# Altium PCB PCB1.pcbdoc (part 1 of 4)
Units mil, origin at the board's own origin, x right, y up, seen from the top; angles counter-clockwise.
Board outline 4701.34 x 4268.46 mil, 2 copper layers (Top Layer, Bottom Layer); 341 components, 58 nets, 1384 pads, 312 vias.
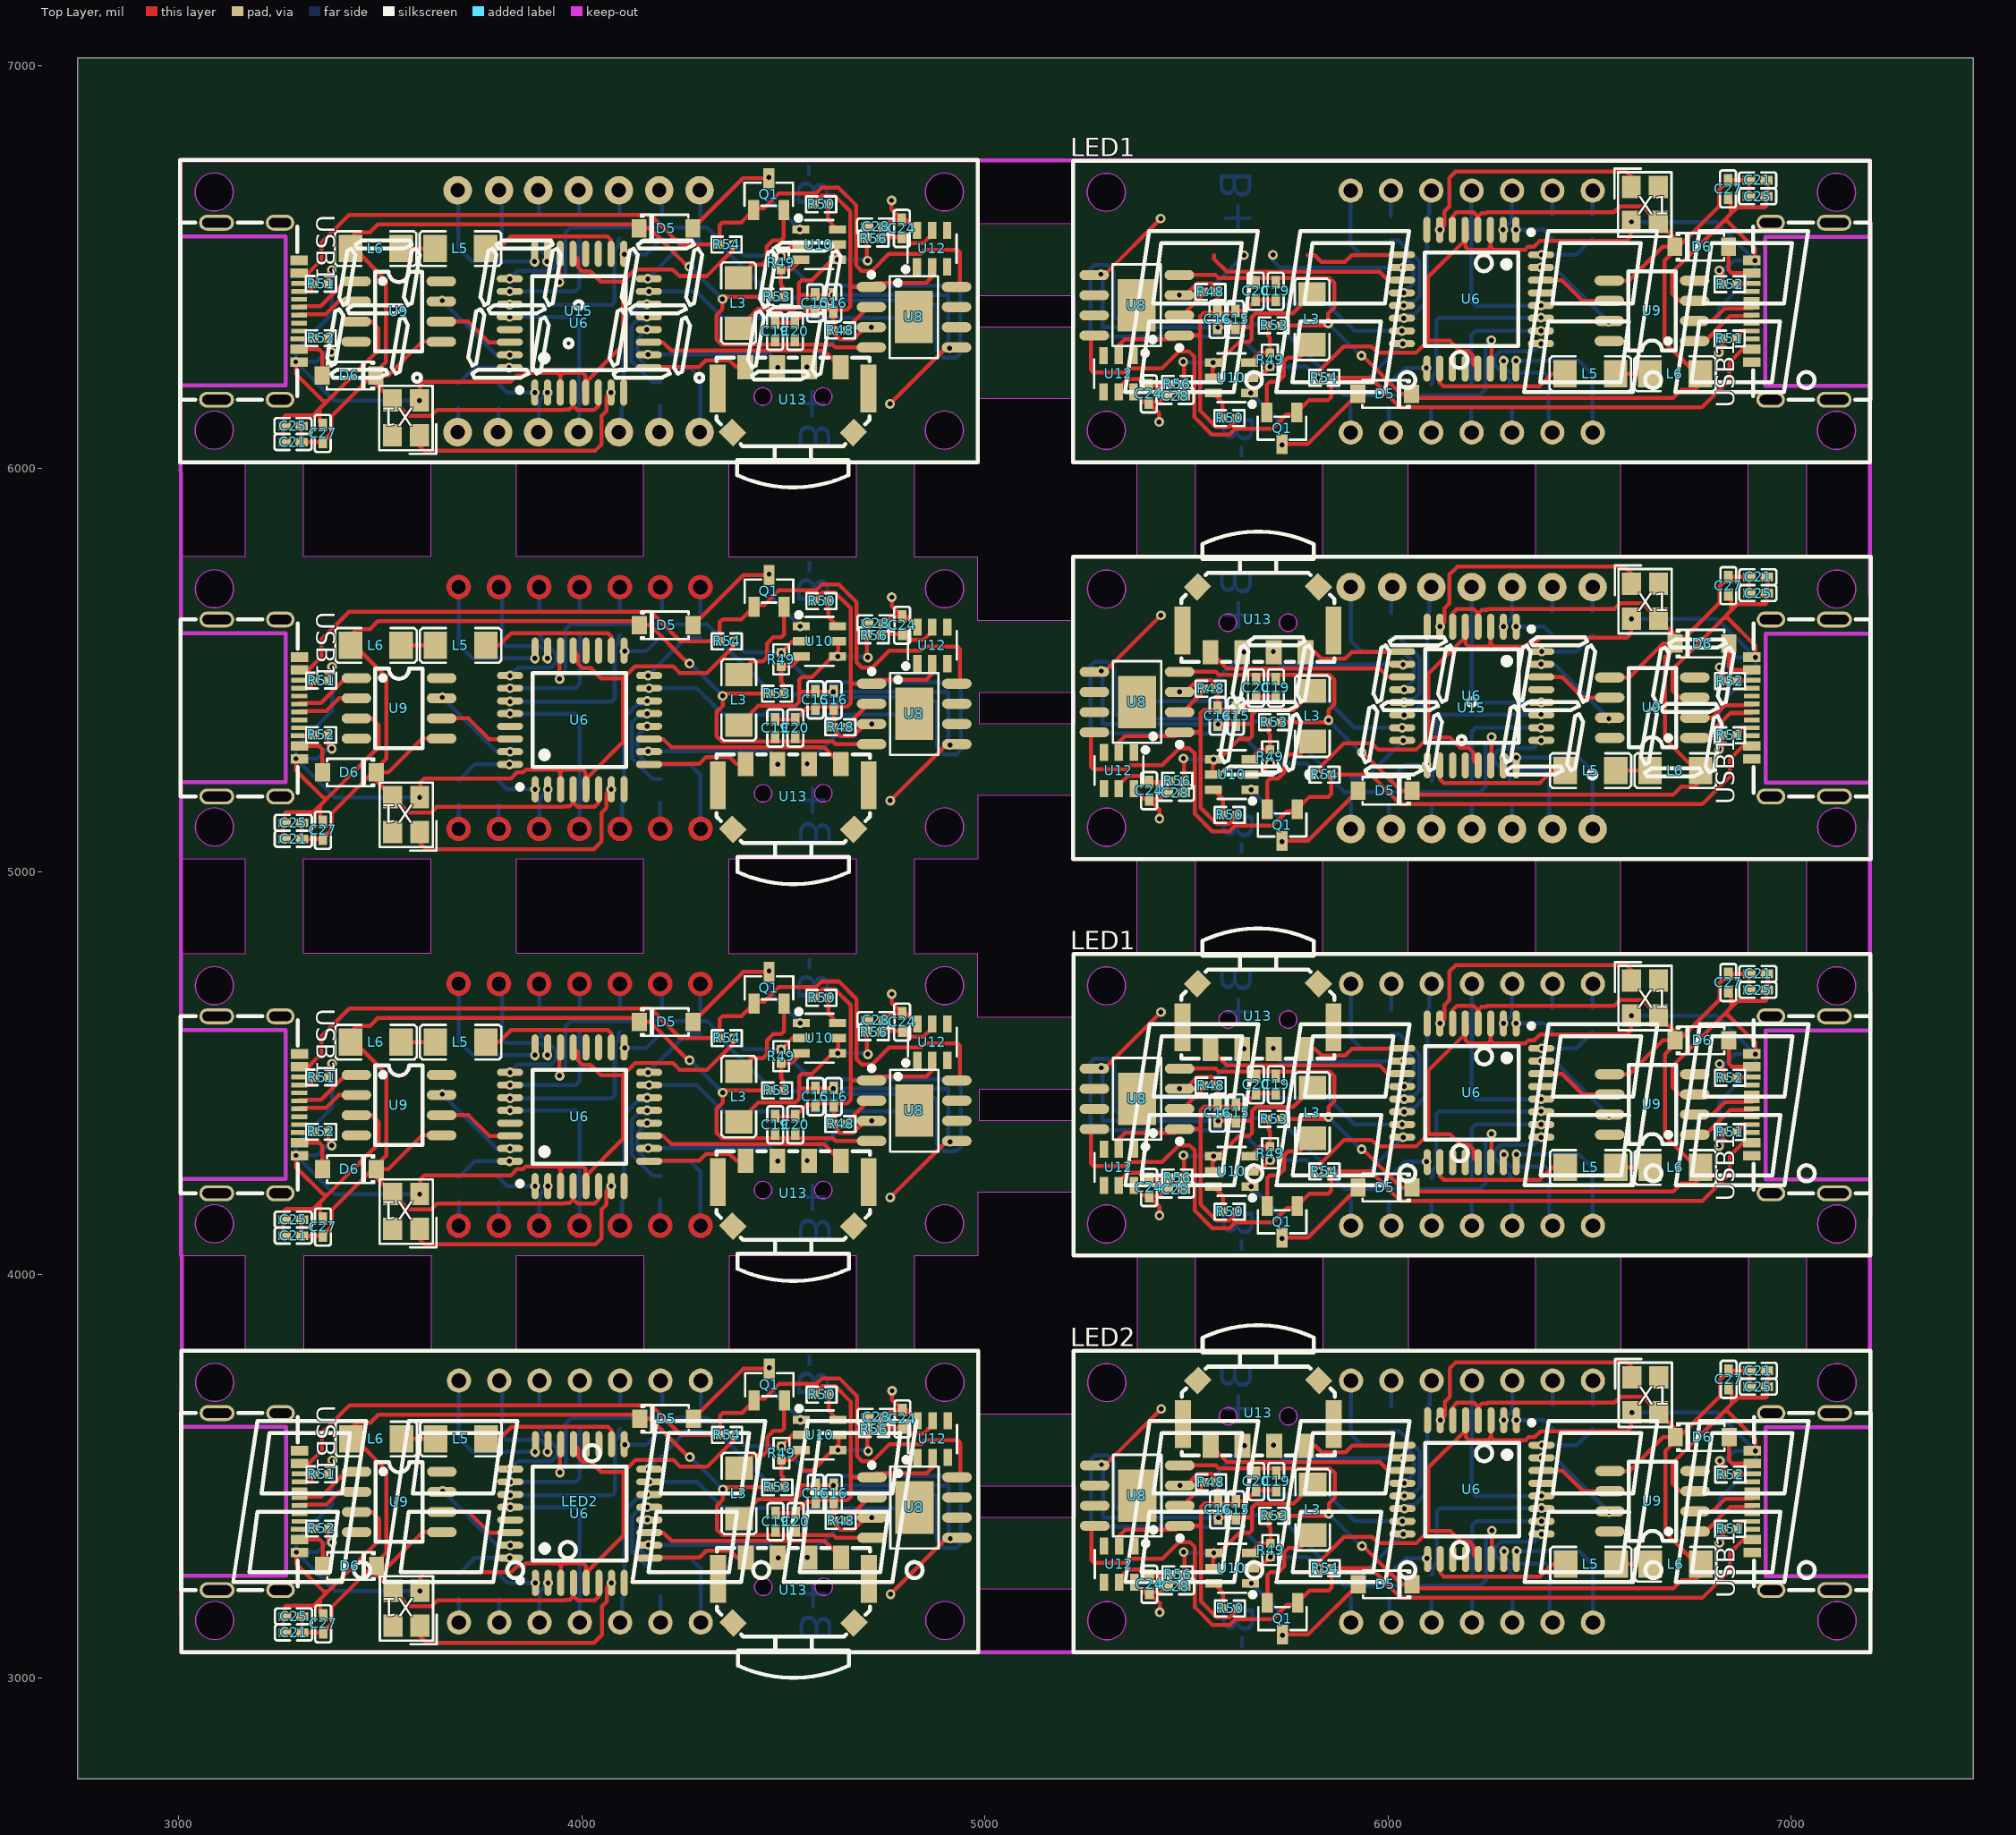
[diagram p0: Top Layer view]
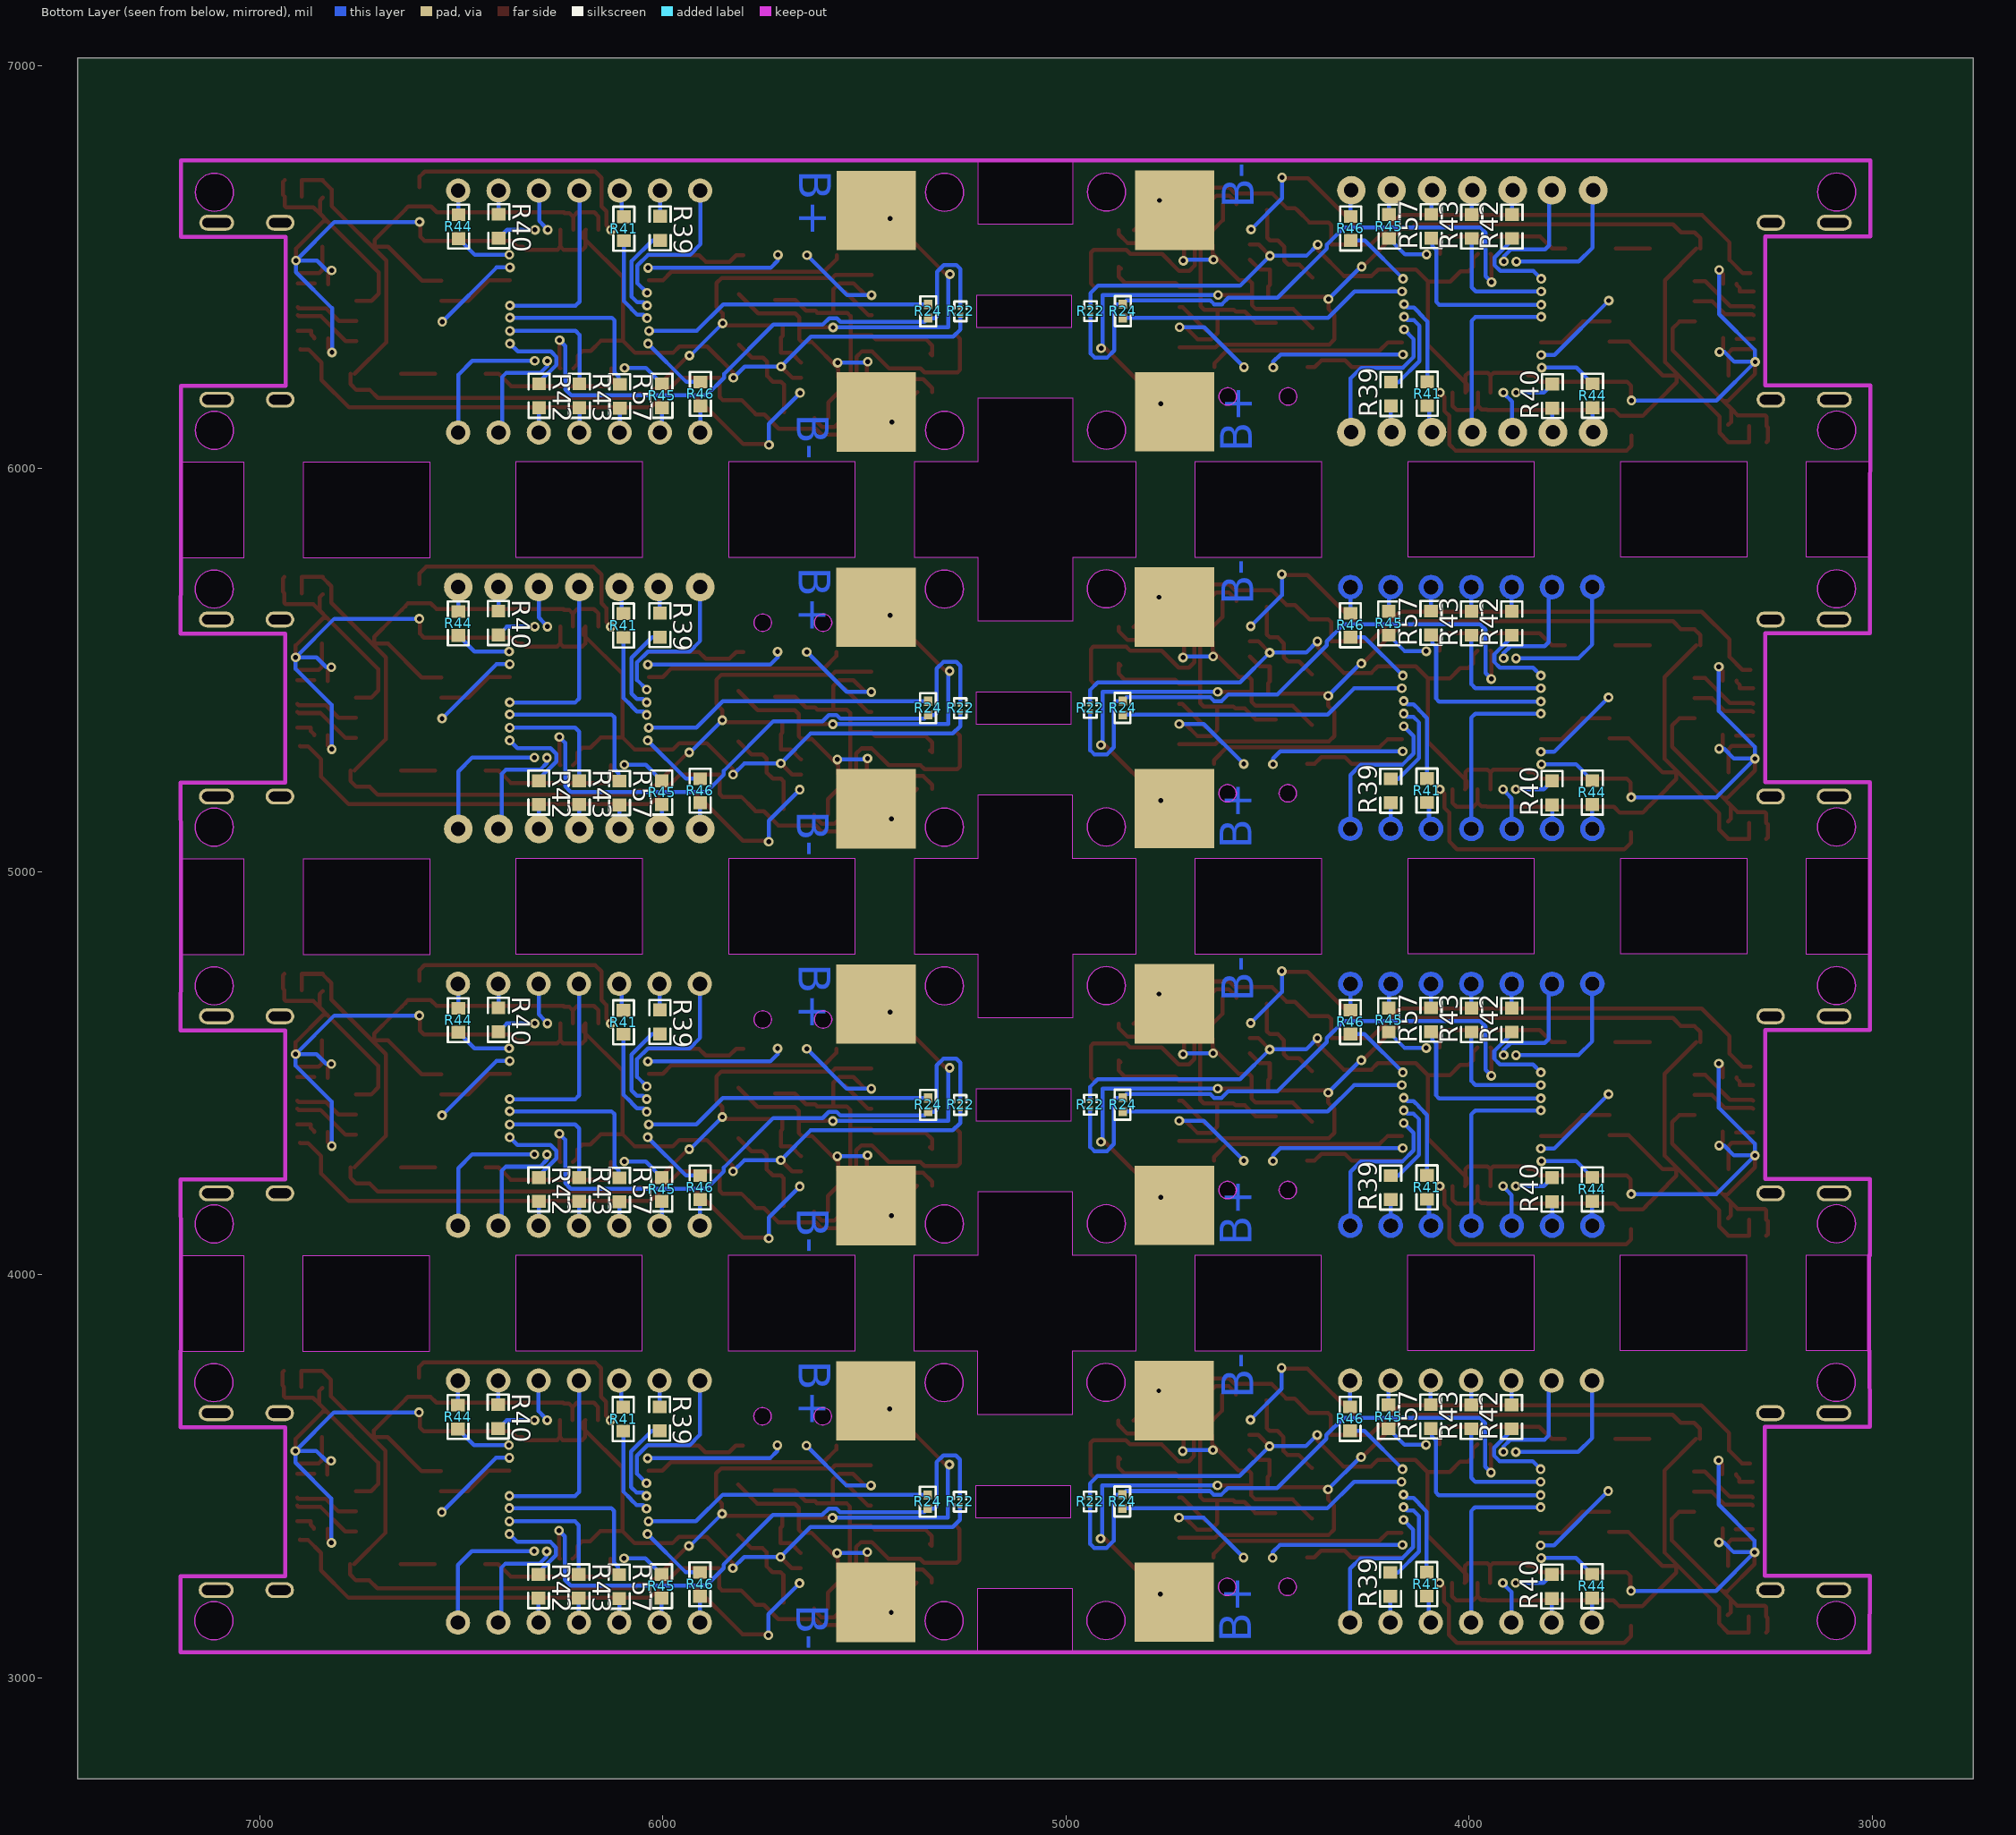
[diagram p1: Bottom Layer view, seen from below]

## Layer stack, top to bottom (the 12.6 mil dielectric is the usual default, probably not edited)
Top Layer: signal copper (thickness not stored)
Dielectric: dielectric 12.6, FR-4, Dk 4.8
Bottom Layer: signal copper (thickness not stored)

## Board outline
7451.34,2750 2750,2750 2750,7018.46 7451.34,7018.46
cut-out: 3136.51,5701.61 cw(c3089.27,5701.61) 3042.02,5701.61 cw(c3089.27,5701.61)
cut-out: 4947.53,5701.61 cw(c4900.29,5701.61) 4853.05,5701.61 cw(c4900.29,5701.61)
cut-out: 5349.12,5701.11 cw(c5301.87,5701.11) 5254.63,5701.11 cw(c5301.87,5701.11)
cut-out: 7160.14,5701.11 cw(c7112.9,5701.11) 7065.65,5701.11 cw(c7112.9,5701.11)
cut-out: 4987.01,5366.71 4987.01,5445.45 5223.23,5445.45 5223.23,5366.71
cut-out: 3136.51,4717.36 cw(c3089.27,4717.36) 3042.02,4717.36 cw(c3089.27,4717.36)
cut-out: 3448.26,5032.78 3625.43,5032.78 3625.43,4796.56 3310.47,4796.56 3310.47,5032.78
cut-out: 4522.97,5032.05 4680.45,5032.05 4680.45,4795.83 4365.49,4795.83 4365.49,5032.05
cut-out: 4947.53,4717.36 cw(c4900.29,4717.36) 4853.05,4717.36 cw(c4900.29,4717.36)
cut-out: 3971.89,5032.78 4152.99,5032.78 4152.99,4796.56 3838.03,4796.56 3838.03,5032.78
cut-out: 5349.12,4716.85 cw(c5301.87,4716.85) 5254.63,4716.85 cw(c5301.87,4716.85)
cut-out: 5679.92,5032.07 5837.4,5032.07 5837.4,4795.85 5522.44,4795.85 5522.44,5032.07
cut-out: 6207.48,5032.07 6364.96,5032.07 6364.96,4795.85 6050,4795.85 6050,5032.07
cut-out: 6734.94,5031.34 6892.42,5031.34 6892.42,4795.12 6577.46,4795.12 6577.46,5031.34
cut-out: 7160.14,4716.85 cw(c7112.9,4716.85) 7065.65,4716.85 cw(c7112.9,4716.85)
cut-out: 3136.51,5111.06 cw(c3089.27,5111.06) 3042.02,5111.06 cw(c3089.27,5111.06)
cut-out: 5376.77,4795.85 5219.29,4795.85 5219.29,4791.91 5219.19,4791.91 5219.19,4638.62 4982.97,4638.62 4982.97,4795.83 4826.12,4795.83 4825.59,4795.85 4825.59,5032.07 4983.07,5032.07 4983.07,5189.55 5219.29,5189.55 5219.29,5032.07 5376.77,5032.07
cut-out: 4947.53,5111.06 cw(c4900.29,5111.06) 4853.05,5111.06 cw(c4900.29,5111.06)
cut-out: 5349.12,5110.55 cw(c5301.87,5110.55) 5254.63,5110.55 cw(c5301.87,5110.55)
cut-out: 7160.14,5110.55 cw(c7112.9,5110.55) 7065.65,5110.55 cw(c7112.9,5110.55)
cut-out: 3136.51,4126.81 cw(c3089.27,4126.81) 3042.02,4126.81 cw(c3089.27,4126.81)
cut-out: 3539.48,3812.31 3311.14,3812.31 3311.14,4048.53 3626.1,4048.53 3626.1,3812.31
cut-out: 4523.64,4047.8 4681.12,4047.8 4681.12,3811.58 4366.16,3811.58 4366.16,4047.8
cut-out: 4947.53,4126.81 cw(c4900.29,4126.81) 4853.05,4126.81 cw(c4900.29,4126.81)
cut-out: 4063.11,3812.31 3838.7,3812.31 3838.7,4048.53 4153.66,4048.53 4153.66,3812.31
cut-out: 4987.01,4382.46 4987.01,4461.2 5223.23,4461.2 5223.23,4382.46
cut-out: 5349.12,4126.3 cw(c5301.87,4126.3) 5254.63,4126.3 cw(c5301.87,4126.3)
cut-out: 5653.03,4047.82 5838.07,4047.82 5838.07,3811.6 5523.11,3811.6 5523.11,4047.82
cut-out: 7160.14,4126.3 cw(c7112.9,4126.3) 7065.65,4126.3 cw(c7112.9,4126.3)
cut-out: 6208.15,4047.82 6365.63,4047.82 6365.63,3811.6 6050.67,3811.6 6050.67,4047.82
cut-out: 6735.61,4047.08 6893.09,4047.08 6893.09,3810.86 6578.13,3810.86 6578.13,4047.08
cut-out: 3137.18,3142.56 cw(c3089.94,3142.56) 3042.69,3142.56 cw(c3089.94,3142.56)
cut-out: 4948.2,3142.56 cw(c4900.96,3142.56) 4853.71,3142.56 cw(c4900.96,3142.56)
cut-out: 4987.68,3398.21 4987.68,3476.95 5223.9,3476.95 5223.9,3398.21
cut-out: 5349.78,3142.05 cw(c5302.54,3142.05) 5255.3,3142.05 cw(c5302.54,3142.05)
cut-out: 7160.81,3142.05 cw(c7113.56,3142.05) 7066.32,3142.05 cw(c7113.56,3142.05)
cut-out: 3137.18,3733.11 cw(c3089.94,3733.11) 3042.69,3733.11 cw(c3089.94,3733.11)
cut-out: 5219.29,4205.3 5219.29,4047.82 5377.44,4047.82 5377.44,3811.6 5219.96,3811.6 5219.96,3807.66 5219.86,3807.66 5219.86,3654.37 4983.64,3654.37 4983.64,3811.58 4826.79,3811.58 4826.26,3811.6 4826.26,4047.82 4983.07,4047.82 4983.07,4205.3
cut-out: 4948.2,3733.11 cw(c4900.96,3733.11) 4853.71,3733.11 cw(c4900.96,3733.11)
cut-out: 5349.78,3732.6 cw(c5302.54,3732.6) 5255.3,3732.6 cw(c5302.54,3732.6)
cut-out: 7160.81,3732.6 cw(c7113.56,3732.6) 7066.32,3732.6 cw(c7113.56,3732.6)
cut-out: 3135.84,6095.32 cw(c3088.6,6095.32) 3041.35,6095.32 cw(c3088.6,6095.32)
cut-out: 3135.84,6685.87 cw(c3088.6,6685.87) 3041.35,6685.87 cw(c3088.6,6685.87)
cut-out: 3538.82,5780.82 3310.47,5780.82 3310.47,6017.04 3625.43,6017.04 3625.43,5780.82
cut-out: 4062.44,5780.82 3838.03,5780.82 3838.03,6017.04 4152.99,6017.04 4152.99,5780.82
cut-out: 4946.87,6095.32 cw(c4899.62,6095.32) 4852.38,6095.32 cw(c4899.62,6095.32)
cut-out: 4946.87,6685.87 cw(c4899.62,6685.87) 4852.38,6685.87 cw(c4899.62,6685.87)
cut-out: 4986.34,6350.97 4986.34,6429.71 5222.56,6429.71 5222.56,6350.97
cut-out: 5348.45,6685.36 cw(c5301.2,6685.36) 5253.96,6685.36 cw(c5301.2,6685.36)
cut-out: 5348.45,6094.81 cw(c5301.2,6094.81) 5253.96,6094.81 cw(c5301.2,6094.81)
cut-out: 5652.36,6016.32 5837.4,6016.32 5837.4,5780.1 5522.44,5780.1 5522.44,6016.32
cut-out: 6207.48,6016.32 6364.96,6016.32 6364.96,5780.1 6050,5780.1 6050,6016.32
cut-out: 6734.94,6015.59 6892.42,6015.59 6892.42,5779.37 6577.46,5779.37 6577.46,6015.59
cut-out: 7159.47,6685.36 cw(c7112.23,6685.36) 7064.98,6685.36 cw(c7112.23,6685.36)
cut-out: 7159.47,6094.81 cw(c7112.23,6094.81) 7064.98,6094.81 cw(c7112.23,6094.81)
cut-out: 5218.52,6760.42 5218.52,6607.13 4982.3,6607.13 4982.3,6764.34 4983.33,6764.35 5218.62,6764.35 5218.62,6760.42
cut-out: 7195.57,6015.59 7195.57,5779.37 7038.09,5779.37 7038.09,6015.59
cut-out: 4680.45,6016.3 4680.45,5780.08 4365.49,5780.08 4365.49,6016.3
cut-out: 5219.19,5776.16 5219.19,5622.87 4982.97,5622.87 4982.97,5780.08 4826.12,5780.08 4825.59,5780.1 4825.59,6016.32 4982.4,6016.32 4982.4,6173.8 5218.62,6173.8 5218.62,6016.32 5376.77,6016.32 5376.77,5780.1 5219.29,5780.1 5219.29,5776.16
cut-out: 3165.47,4048.53 3165.47,3812.31 3007.99,3812.31 3007.99,4048.53
cut-out: 5219.96,3221.04 5219.96,3063.56 4983.74,3063.56 4983.74,3221.04
cut-out: 7038.76,3810.86 7038.76,4047.08 7196.24,4047.08 7196.24,3810.86
cut-out: 3006.59,4796.1 3006.59,5032.32 3164.8,5032.78 3164.8,4795.89 3164.59,4796.1
cut-out: 7195.57,5031.34 7195.57,4795.12 7038.09,4795.12 7038.09,5031.34
cut-out: 3003.38,5780.82 3003.38,6017.04 3164.8,6017.04 3164.8,5780.82

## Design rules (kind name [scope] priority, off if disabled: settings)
BoardOutlineClearance copperThickness1oz [All] p0: genericclearance=10 ignorepadtopadclearanceinfootprint=FALSE except(0: Arc-SplitContinuation Track-SplitContinuation SMDPad-SplitContinuation THPad-SplitContinuation Via-SplitContinuation Fill-SplitContinuation Poly-SplitContinuation Region-SplitContinuation Text-SplitContinuation; 6: Track-CutoutEdge SMDPad-CutoutEdge THPad-CutoutEdge Via-CutoutEdge Region-CutoutEdge; 11.8: Track-OutlineEdge SMDPad-OutlineEdge THPad-OutlineEdge Via-OutlineEdge Fill-OutlineEdge Region-OutlineEdge Poly-OutlineEdge Text-OutlineEdge Fill-CutoutEdge)
BoardOutlineClearance copperThickness2oz [All] p0: genericclearance=10 ignorepadtopadclearanceinfootprint=FALSE except(0: Arc-SplitContinuation Track-SplitContinuation SMDPad-SplitContinuation THPad-SplitContinuation Via-SplitContinuation Fill-SplitContinuation Poly-SplitContinuation Region-SplitContinuation Text-SplitContinuation; 6: Track-CutoutEdge SMDPad-CutoutEdge THPad-CutoutEdge Via-CutoutEdge Region-CutoutEdge; 11.8: Track-OutlineEdge SMDPad-OutlineEdge THPad-OutlineEdge Via-OutlineEdge Fill-OutlineEdge Region-OutlineEdge Poly-OutlineEdge Text-OutlineEdge Fill-CutoutEdge)
Clearance copperThickness1oz [(InNet('POWER_VBUS') OR InNet('BATT') OR InNet('$1N14246') OR InNet('POWER_GND') OR InNet('$1N14266') OR InNet('$1N10863') OR InNet('+5V') OR InNet('D7') OR InNet('$1N7885') OR InNet('$1N11526') OR InNet('$1N13433') OR InNet('$1N13465') OR InNet('D5') OR InNet('$1N11705') OR InNet('XTAL1') OR InNet('A7') OR InNet('RX') OR InNet('$1N13291') OR InNet('D+') OR InNet('D-') OR InNet('$1N3744') OR InNet('D6') OR InNet('$1N25016') OR InNet('D8') OR InNet('D12') OR InNet('$1N25014') OR InNet('$1N25004') OR InNet('D9') OR InNet('D13') OR InNet('D11') OR InNet('D10') OR InNet('$1N25012') OR InNet('$1N26871') OR InNet('A4') OR InNet('$1N25022') OR InNet('A3') OR InNet('A2') OR InNet('A0') OR InNet('D4') OR InNet('$1N25024') OR InNet('D3') OR InNet('A1') OR InNet('$1N25008') OR InNet('D2') OR InNet('TX') OR InNet('$1N25046') OR InNet('A5') OR InNet('A6') OR InNet('$1N29845') OR InNet('$1N31836') OR InNet('$1N31834') OR InNet('$1N31838') OR InNet('$1N31830') OR InNet('$1N31828') OR InNet('$1N31832') OR InNet('$1N31824') OR InNet('$1N31826') OR InNet('$1N31822'))] p1: gap=7 ignorepadtopadclearanceinfootprint=FALSE except(4: Track-Track; 6: Track-SMDPad SMDPad-SMDPad Track-THPad SMDPad-THPad THPad-THPad Track-Via SMDPad-Via THPad-Via Via-Via SMDPad-Fill THPad-Fill Via-Fill Fill-Fill Track-Region SMDPad-Region THPad-Region Via-Region Region-Region Track-Poly SMDPad-Poly THPad-Poly Via-Poly Fill-Poly Region-Poly Poly-Poly Track-Text SMDPad-Text THPad-Text Via-Text Fill-Text Region-Text Poly-Text Text-Text; 6.9: Track-Hole SMDPad-Hole THPad-Hole Via-Hole Fill-Hole Region-Hole Poly-Hole Text-Hole Sheet-Hole; 11.8: Track-Fill Fill-Region Track-Sheet SMDPad-Sheet THPad-Sheet Via-Sheet Fill-Sheet Region-Sheet Poly-Sheet Text-Sheet)
Clearance copperThickness2oz [All] p1: gap=7 ignorepadtopadclearanceinfootprint=FALSE except(6: Track-SMDPad SMDPad-SMDPad Track-THPad SMDPad-THPad THPad-THPad Track-Via SMDPad-Via THPad-Via Via-Via SMDPad-Fill THPad-Fill Via-Fill Fill-Fill Track-Region SMDPad-Region THPad-Region Via-Region Region-Region Track-Poly SMDPad-Poly THPad-Poly Via-Poly Fill-Poly Region-Poly Poly-Poly Track-Text SMDPad-Text THPad-Text Via-Text Fill-Text Region-Text Poly-Text Text-Text; 6.9: Track-Hole SMDPad-Hole THPad-Hole Via-Hole Fill-Hole Region-Hole Poly-Hole Text-Hole Sheet-Hole; 8: Track-Track; 11.8: Track-Fill Fill-Region Track-Sheet SMDPad-Sheet THPad-Sheet Via-Sheet Fill-Sheet Region-Sheet Poly-Sheet Text-Sheet)
DiffPairsRouting differentialPair [All] p1: maxuncoupledlength=10 minlimit=6 maxlimit=6 mostfreqgap=6 toplayer_minwidth=5 toplayer_prefwidth=10 toplayer_maxwidth=100 bottomlayer_minwidth=5 bottomlayer_prefwidth=10 bottomlayer_maxwidth=100
PasteMaskExpansion pasteMaskExpansion [All] p1: expansion=0
PlaneConnect innerPlane [All] p1: planeconnectstyle=Relief reliefexpansion=20 reliefentries=4 reliefconductorwidth=10 reliefairgap=10
PolygonConnect copperRegion [All] p1: connectstyle=Relief reliefentries=4 reliefconductorwidth=10 polygonreliefangle="90 Angle" airgapwidth=10
RoutingVias viaSize [All] p1: viastyle="Through Hole" holewidth=12.0078 minholewidth=11.811 maxholewidth=248.0314 width=24.0158 minwidth=19.685 maxwidth=393.7008
SolderMaskExpansion solderMaskExpansion [All] p1: useseparateexpansions=TRUE expansion=2 expansionbottom=2
Width copperThickness1oz [All] p1: maxlimit=100 minlimit=5 preferedwidth=10
Width copperThickness2oz [All] p1: maxlimit=100 minlimit=8 preferedwidth=10

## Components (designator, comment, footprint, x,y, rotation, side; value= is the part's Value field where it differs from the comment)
C15 "CL05A475MQ5NRNC_C307423" C0402 5623.05,3417.33 r90 top
C15 "CL05A475MQ5NRNC_C307423" C0402 4580.45,3457.83 r270 top
C15 "CL05A475MQ5NRNC_C307423" C0402 4579.78,4442.09 r270 top
C15 "CL05A475MQ5NRNC_C307423" C0402 5622.38,4401.58 r90 top
C15 "CL05A475MQ5NRNC_C307423" C0402 4579.78,5426.34 r270 top
C15 "CL05A475MQ5NRNC_C307423" C0402 5622.38,5385.83 r90 top
C15 "CL05A475MQ5NRNC_C307423" C0402 4579.11,6410.59 r270 top
C15 "CL05A475MQ5NRNC_C307423" C0402 5621.72,6370.08 r90 top
C16 "CL05A475MQ5NRNC_C307423" C0402 5578.05,3417.33 r90 top
C16 "CL05A475MQ5NRNC_C307423" C0402 4625.45,3457.83 r270 top
C16 "CL05A475MQ5NRNC_C307423" C0402 4624.78,4442.09 r270 top
C16 "CL05A475MQ5NRNC_C307423" C0402 5577.38,4401.58 r90 top
C16 "CL05A475MQ5NRNC_C307423" C0402 4624.78,5426.34 r270 top
C16 "CL05A475MQ5NRNC_C307423" C0402 5577.38,5385.83 r90 top
C16 "CL05A475MQ5NRNC_C307423" C0402 4624.11,6410.59 r270 top
C16 "CL05A475MQ5NRNC_C307423" C0402 5576.72,6370.08 r90 top
C19 "CL05A475MQ5NRNC_C307423" C0402 5722.59,3487.33 r90 top
C19 "CL05A475MQ5NRNC_C307423" C0402 4480.91,3387.83 r270 top
C19 "CL05A475MQ5NRNC_C307423" C0402 4480.24,4372.09 r270 top
C19 "CL05A475MQ5NRNC_C307423" C0402 5721.92,4471.58 r90 top
C19 "CL05A475MQ5NRNC_C307423" C0402 4480.24,5356.34 r270 top
C19 "CL05A475MQ5NRNC_C307423" C0402 5721.92,5455.83 r90 top
C19 "CL05A475MQ5NRNC_C307423" C0402 4479.57,6340.59 r270 top
C19 "CL05A475MQ5NRNC_C307423" C0402 5721.26,6440.08 r90 top
C20 "CL05A475MQ5NRNC_C307423" C0402 5673.05,3487.33 r90 top
C20 "CL05A475MQ5NRNC_C307423" C0402 4530.45,3387.83 r270 top
C20 "CL05A475MQ5NRNC_C307423" C0402 4529.78,4372.09 r270 top
C20 "CL05A475MQ5NRNC_C307423" C0402 5672.38,4471.58 r90 top
C20 "CL05A475MQ5NRNC_C307423" C0402 4529.78,5356.34 r270 top
C20 "CL05A475MQ5NRNC_C307423" C0402 5672.38,5455.83 r90 top
C20 "CL05A475MQ5NRNC_C307423" C0402 4529.11,6340.59 r270 top
C20 "CL05A475MQ5NRNC_C307423" C0402 5671.72,6440.08 r90 top
C21 "CL05A475MQ5NRNC_C307423" C0402 6918.05,3762.33 r0 top
C21 "CL05A475MQ5NRNC_C307423" C0402 3285.45,3112.83 r180 top
C21 "CL05A475MQ5NRNC_C307423" C0402 3284.78,4097.09 r180 top
C21 "CL05A475MQ5NRNC_C307423" C0402 6917.38,4746.58 r0 top
C21 "CL05A475MQ5NRNC_C307423" C0402 3284.78,5081.34 r180 top
C21 "CL05A475MQ5NRNC_C307423" C0402 6917.38,5730.83 r0 top
C21 "CL05A475MQ5NRNC_C307423" C0402 3284.11,6065.59 r180 top
C21 "CL05A475MQ5NRNC_C307423" C0402 6916.72,6715.08 r0 top
C24 "FCC0402B104K160AT" C0402 5408.05,3232.33 r270 top
C24 "FCC0402B104K160AT" C0402 4795.45,3642.83 r90 top
C24 "FCC0402B104K160AT" C0402 4794.78,4627.09 r90 top
C24 "FCC0402B104K160AT" C0402 5407.38,4216.58 r270 top
C24 "FCC0402B104K160AT" C0402 4794.78,5611.34 r90 top
C24 "FCC0402B104K160AT" C0402 5407.38,5200.83 r270 top
C24 "FCC0402B104K160AT" C0402 4794.11,6595.59 r90 top
C24 "FCC0402B104K160AT" C0402 5406.72,6185.08 r270 top
C25 "CL05A475MQ5NRNC_C307423" C0402 6918.05,3722.33 r180 top
C25 "CL05A475MQ5NRNC_C307423" C0402 3285.45,3152.83 r0 top
C25 "CL05A475MQ5NRNC_C307423" C0402 3284.78,4137.09 r0 top
C25 "CL05A475MQ5NRNC_C307423" C0402 6917.38,4706.58 r180 top
C25 "CL05A475MQ5NRNC_C307423" C0402 3284.78,5121.34 r0 top
C25 "CL05A475MQ5NRNC_C307423" C0402 6917.38,5690.83 r180 top
C25 "CL05A475MQ5NRNC_C307423" C0402 3284.11,6105.59 r0 top
C25 "CL05A475MQ5NRNC_C307423" C0402 6916.72,6675.08 r180 top
C27 "CL05A475MQ5NRNC_C307423" C0402 6844.51,3740.87 r90 top
C27 "CL05A475MQ5NRNC_C307423" C0402 3358.99,3134.29 r270 top
C27 "CL05A475MQ5NRNC_C307423" C0402 3358.32,4118.55 r270 top
C27 "CL05A475MQ5NRNC_C307423" C0402 6843.84,4725.12 r90 top
C27 "CL05A475MQ5NRNC_C307423" C0402 3358.32,5102.8 r270 top
C27 "CL05A475MQ5NRNC_C307423" C0402 6843.84,5709.37 r90 top
C27 "CL05A475MQ5NRNC_C307423" C0402 3357.65,6087.05 r270 top
C27 "CL05A475MQ5NRNC_C307423" C0402 6843.18,6693.62 r90 top
C28 "CL05A475MQ5NRNC_C307423" C0402 5473.05,3227.33 r0 top
C28 "CL05A475MQ5NRNC_C307423" C0402 4730.45,3647.83 r180 top
C28 "CL05A475MQ5NRNC_C307423" C0402 4729.78,4632.09 r180 top
C28 "CL05A475MQ5NRNC_C307423" C0402 5472.38,4211.58 r0 top
C28 "CL05A475MQ5NRNC_C307423" C0402 4729.78,5616.34 r180 top
C28 "CL05A475MQ5NRNC_C307423" C0402 5472.38,5195.83 r0 top
C28 "CL05A475MQ5NRNC_C307423" C0402 4729.11,6600.59 r180 top
C28 "CL05A475MQ5NRNC_C307423" C0402 5471.72,6180.08 r0 top
D5 "DSK34_C41029" SOD-123_L2.8-W1.8-LS3.7-RD 5993.05,3232.33 r180 top
D5 "DSK34_C41029" SOD-123_L2.8-W1.8-LS3.7-RD 4210.45,3642.83 r0 top
D5 "DSK34_C41029" SOD-123_L2.8-W1.8-LS3.7-RD 4209.78,4627.09 r0 top
D5 "DSK34_C41029" SOD-123_L2.8-W1.8-LS3.7-RD 5992.38,4216.58 r180 top
D5 "DSK34_C41029" SOD-123_L2.8-W1.8-LS3.7-RD 4209.78,5611.34 r0 top
D5 "DSK34_C41029" SOD-123_L2.8-W1.8-LS3.7-RD 5992.38,5200.83 r180 top
D5 "DSK34_C41029" SOD-123_L2.8-W1.8-LS3.7-RD 4209.11,6595.59 r0 top
D5 "DSK34_C41029" SOD-123_L2.8-W1.8-LS3.7-RD 5991.72,6185.08 r180 top
D6 "DSK34_C41029" SOD-123_L2.8-W1.8-LS3.7-RD 6779.12,3597.33 r0 top
D6 "DSK34_C41029" SOD-123_L2.8-W1.8-LS3.7-RD 3424.38,3277.83 r180 top
D6 "DSK34_C41029" SOD-123_L2.8-W1.8-LS3.7-RD 3423.72,4262.09 r180 top
D6 "DSK34_C41029" SOD-123_L2.8-W1.8-LS3.7-RD 6778.45,4581.58 r0 top
D6 "DSK34_C41029" SOD-123_L2.8-W1.8-LS3.7-RD 3423.72,5246.34 r180 top
D6 "DSK34_C41029" SOD-123_L2.8-W1.8-LS3.7-RD 6778.45,5565.83 r0 top
D6 "DSK34_C41029" SOD-123_L2.8-W1.8-LS3.7-RD 3423.05,6230.59 r180 top
D6 "DSK34_C41029" SOD-123_L2.8-W1.8-LS3.7-RD 6777.78,6550.08 r0 top
L3 "CMI321609U4R7KT" L1206 5813.05,3417.33 r270 top
L3 "CMI321609U4R7KT" L1206 4390.45,3457.83 r90 top
L3 "CMI321609U4R7KT" L1206 4389.78,4442.09 r90 top
L3 "CMI321609U4R7KT" L1206 5812.38,4401.58 r270 top
L3 "CMI321609U4R7KT" L1206 4389.78,5426.34 r90 top
L3 "CMI321609U4R7KT" L1206 5812.38,5385.83 r270 top
L3 "CMI321609U4R7KT" L1206 4389.11,6410.59 r90 top
L3 "CMI321609U4R7KT" L1206 5811.72,6370.08 r270 top
L5 "CMI321609U4R7KT" L1206 6503.05,3282.33 r180 top
L5 "CMI321609U4R7KT" L1206 3700.45,3592.83 r0 top
L5 "CMI321609U4R7KT" L1206 3699.78,4577.09 r0 top
L5 "CMI321609U4R7KT" L1206 6502.38,4266.58 r180 top
L5 "CMI321609U4R7KT" L1206 3699.78,5561.34 r0 top
L5 "CMI321609U4R7KT" L1206 6502.38,5250.83 r180 top
L5 "CMI321609U4R7KT" L1206 3699.11,6545.59 r0 top
L5 "CMI321609U4R7KT" L1206 6501.72,6235.08 r180 top
L6 "CMI321609U4R7KT" L1206 6713.05,3282.33 r180 top
L6 "CMI321609U4R7KT" L1206 3490.45,3592.83 r0 top
L6 "CMI321609U4R7KT" L1206 3489.78,4577.09 r0 top
L6 "CMI321609U4R7KT" L1206 6712.38,4266.58 r180 top
L6 "CMI321609U4R7KT" L1206 3489.78,5561.34 r0 top
L6 "CMI321609U4R7KT" L1206 6712.38,5250.83 r180 top
L6 "CMI321609U4R7KT" L1206 3489.11,6545.59 r0 top
L6 "CMI321609U4R7KT" L1206 6711.72,6235.08 r180 top
LED1 "SLR0564DBA4BD" LED-SEG-TH_SLR0564DBA4BD 6208.15,4421.83 r0 top
LED1 "SLR0564DBA4BD" LED-SEG-TH_SLR0564DBA4BD 6207.45,6389.45 r0 top
LED2 "SLRR0564DY2C4BD-6.3" LED-SEG-TH_SLRR0564DY2C4BD-6.3 6208.15,3437.58 r0 top
LED2 "SLRR0564DY2C4BD-6.3" LED-SEG-TH_SLRR0564DY2C4BD-6.3 3995.55,3437.58 r0 top
Q1 "IRLML6401_C5190144" SOT-23-3_L2.9-W1.3-P1.90-LS2.4-BR 5738.05,3147.33 r90 top
Q1 "IRLML6401_C5190144" SOT-23-3_L2.9-W1.3-P1.90-LS2.4-BR 4465.45,3727.83 r270 top
Q1 "IRLML6401_C5190144" SOT-23-3_L2.9-W1.3-P1.90-LS2.4-BR 4464.78,4712.09 r270 top
Q1 "IRLML6401_C5190144" SOT-23-3_L2.9-W1.3-P1.90-LS2.4-BR 5737.38,4131.58 r90 top
Q1 "IRLML6401_C5190144" SOT-23-3_L2.9-W1.3-P1.90-LS2.4-BR 4464.78,5696.34 r270 top
Q1 "IRLML6401_C5190144" SOT-23-3_L2.9-W1.3-P1.90-LS2.4-BR 5737.38,5115.83 r90 top
Q1 "IRLML6401_C5190144" SOT-23-3_L2.9-W1.3-P1.90-LS2.4-BR 4464.11,6680.59 r270 top
Q1 "IRLML6401_C5190144" SOT-23-3_L2.9-W1.3-P1.90-LS2.4-BR 5736.72,6100.08 r90 top
R22 "100k" R0201 5263.05,3437.33 r270 bottom
R22 "100k" R0201 4940.45,3437.83 r90 bottom
R22 "100k" R0201 4939.78,4422.09 r90 bottom
R22 "100k" R0201 5262.38,4421.58 r270 bottom
R22 "100k" R0201 4939.78,5406.34 r90 bottom
R22 "100k" R0201 5262.38,5405.83 r270 bottom
R22 "100k" R0201 4939.11,6390.59 r90 bottom
R22 "100k" R0201 5261.72,6390.08 r270 bottom
R24 "0402WGF1003TCE" R0402 5343.05,3437.33 r270 bottom
R24 "0402WGF1003TCE" R0402 4860.45,3437.83 r90 bottom
R24 "0402WGF1003TCE" R0402 4859.78,4422.09 r90 bottom
R24 "0402WGF1003TCE" R0402 5342.38,4421.58 r270 bottom
R24 "0402WGF1003TCE" R0402 4859.78,5406.34 r90 bottom
R24 "0402WGF1003TCE" R0402 5342.38,5405.83 r270 bottom
R24 "0402WGF1003TCE" R0402 4859.11,6390.59 r90 bottom
R24 "0402WGF1003TCE" R0402 5341.72,6390.08 r270 bottom
R39 "FRC0603F1001TS" R0603 6008.05,3643.01 r270 bottom
R39 "FRC0603F1001TS" R0603 4195.45,3232.15 r90 bottom
R39 "FRC0603F1001TS" R0603 4194.78,4216.41 r90 bottom
R39 "FRC0603F1001TS" R0603 6007.38,4627.26 r270 bottom
R39 "FRC0603F1001TS" R0603 4194.78,5200.66 r90 bottom
R39 "FRC0603F1001TS" R0603 6007.38,5611.51 r270 bottom
R39 "FRC0603F1001TS" R0603 4194.11,6184.91 r90 bottom
R39 "FRC0603F1001TS" R0603 6006.72,6595.76 r270 bottom
R40 "FRC0603F1001TS" R0603 6408.29,3648.23 r270 bottom
R40 "FRC0603F1001TS" R0603 3795.21,3226.93 r90 bottom
R40 "FRC0603F1001TS" R0603 3794.54,4211.18 r90 bottom
R40 "FRC0603F1001TS" R0603 6407.63,4632.48 r270 bottom
R40 "FRC0603F1001TS" R0603 3794.54,5195.43 r90 bottom
R40 "FRC0603F1001TS" R0603 6407.63,5616.74 r270 bottom
R40 "FRC0603F1001TS" R0603 3793.87,6179.68 r90 bottom
R40 "FRC0603F1001TS" R0603 6406.96,6600.99 r270 bottom
R41 "FRC0603F1001TS" R0603 6098.05,3642.33 r270 bottom
R41 "FRC0603F1001TS" R0603 4105.45,3232.83 r90 bottom
R41 "FRC0603F1001TS" R0603 4104.78,4217.09 r90 bottom
R41 "FRC0603F1001TS" R0603 6097.38,4626.58 r270 bottom
R41 "FRC0603F1001TS" R0603 4104.78,5201.34 r90 bottom
R41 "FRC0603F1001TS" R0603 6097.38,5610.83 r270 bottom
R41 "FRC0603F1001TS" R0603 4104.11,6185.59 r90 bottom
R41 "FRC0603F1001TS" R0603 6096.72,6595.08 r270 bottom
R42 "FRC0603F1001TS" R0603 6308.29,3227.55 r270 bottom
R42 "FRC0603F1001TS" R0603 3895.21,3647.61 r90 bottom
R42 "FRC0603F1001TS" R0603 3894.54,4631.86 r90 bottom
R42 "FRC0603F1001TS" R0603 6307.63,4211.8 r270 bottom
R42 "FRC0603F1001TS" R0603 3894.54,5616.11 r90 bottom
R42 "FRC0603F1001TS" R0603 6307.63,5196.06 r270 bottom
R42 "FRC0603F1001TS" R0603 3893.87,6600.36 r90 bottom
R42 "FRC0603F1001TS" R0603 6306.96,6180.31 r270 bottom
R43 "FRC0603F1001TS" R0603 6208.29,3227.55 r270 bottom
R43 "FRC0603F1001TS" R0603 3995.21,3647.61 r90 bottom
R43 "FRC0603F1001TS" R0603 3994.54,4631.86 r90 bottom
R43 "FRC0603F1001TS" R0603 6207.63,4211.8 r270 bottom
R43 "FRC0603F1001TS" R0603 3994.54,5616.11 r90 bottom
R43 "FRC0603F1001TS" R0603 6207.63,5196.06 r270 bottom
R43 "FRC0603F1001TS" R0603 3993.87,6600.36 r90 bottom
R43 "FRC0603F1001TS" R0603 6206.96,6180.31 r270 bottom
R44 "FRC0603F1001TS" R0603 6508.05,3647.33 r270 bottom
R44 "FRC0603F1001TS" R0603 3695.45,3227.83 r90 bottom
R44 "FRC0603F1001TS" R0603 3694.78,4212.09 r90 bottom
R44 "FRC0603F1001TS" R0603 6507.38,4631.58 r270 bottom
R44 "FRC0603F1001TS" R0603 3694.78,5196.34 r90 bottom
R44 "FRC0603F1001TS" R0603 6507.38,5615.83 r270 bottom
R44 "FRC0603F1001TS" R0603 3694.11,6180.59 r90 bottom
R44 "FRC0603F1001TS" R0603 6506.72,6600.08 r270 bottom
R45 "FRC0603F1001TS" R0603 6003.29,3227.55 r270 bottom
R45 "FRC0603F1001TS" R0603 4200.21,3647.61 r90 bottom
R45 "FRC0603F1001TS" R0603 4199.54,4631.86 r90 bottom
R45 "FRC0603F1001TS" R0603 6002.63,4211.8 r270 bottom
R45 "FRC0603F1001TS" R0603 4199.54,5616.11 r90 bottom
R45 "FRC0603F1001TS" R0603 6002.63,5196.06 r270 bottom
R45 "FRC0603F1001TS" R0603 4198.87,6600.36 r90 bottom
R45 "FRC0603F1001TS" R0603 6001.96,6180.31 r270 bottom
R46 "FRC0603F1001TS" R0603 5908.05,3232.33 r270 bottom
R46 "FRC0603F1001TS" R0603 4295.45,3642.83 r90 bottom
R46 "FRC0603F1001TS" R0603 4294.78,4627.09 r90 bottom
R46 "FRC0603F1001TS" R0603 5907.38,4216.58 r270 bottom
R46 "FRC0603F1001TS" R0603 4294.78,5611.34 r90 bottom
R46 "FRC0603F1001TS" R0603 5907.38,5200.83 r270 bottom
R46 "FRC0603F1001TS" R0603 4294.11,6595.59 r90 bottom
R46 "FRC0603F1001TS" R0603 5906.72,6185.08 r270 bottom
R48 "0402WGF2401TCE" R0402 5561.01,3485.29 r0 top
R48 "0402WGF2401TCE" R0402 4642.49,3389.87 r180 top
R48 "0402WGF2401TCE" R0402 4641.82,4374.13 r180 top
R48 "0402WGF2401TCE" R0402 5560.34,4469.54 r0 top
R48 "0402WGF2401TCE" R0402 4641.82,5358.38 r180 top
R48 "0402WGF2401TCE" R0402 5560.34,5453.79 r0 top
R48 "0402WGF2401TCE" R0402 4641.15,6342.63 r180 top
R48 "0402WGF2401TCE" R0402 5559.68,6438.04 r0 top
R49 "0402WGF2401TCE" R0402 5708.05,3317.33 r270 top
R49 "0402WGF2401TCE" R0402 4495.45,3557.83 r90 top
R49 "0402WGF2401TCE" R0402 4494.78,4542.09 r90 top
R49 "0402WGF2401TCE" R0402 5707.38,4301.58 r270 top
R49 "0402WGF2401TCE" R0402 4494.78,5526.34 r90 top
R49 "0402WGF2401TCE" R0402 5707.38,5285.83 r270 top
R49 "0402WGF2401TCE" R0402 4494.11,6510.59 r90 top
R49 "0402WGF2401TCE" R0402 5706.72,6270.08 r270 top
R50 "0402WGF1003TCE" R0402 5608.05,3172.33 r0 top
R50 "0402WGF1003TCE" R0402 4595.45,3702.83 r180 top
R50 "0402WGF1003TCE" R0402 4594.78,4687.09 r180 top
R50 "0402WGF1003TCE" R0402 5607.38,4156.58 r0 top
R50 "0402WGF1003TCE" R0402 4594.78,5671.34 r180 top
R50 "0402WGF1003TCE" R0402 5607.38,5140.83 r0 top
R50 "0402WGF1003TCE" R0402 4594.11,6655.59 r180 top
R50 "0402WGF1003TCE" R0402 5606.72,6125.08 r0 top
R51 "0402WGF5101TCE" R0402 6848.49,3369.72 r0 top
R51 "0402WGF5101TCE" R0402 3355.01,3505.44 r180 top
R51 "0402WGF5101TCE" R0402 3354.34,4489.69 r180 top
R51 "0402WGF5101TCE" R0402 6847.82,4353.97 r0 top
R51 "0402WGF5101TCE" R0402 3354.34,5473.94 r180 top
R51 "0402WGF5101TCE" R0402 6847.82,5338.22 r0 top
R51 "0402WGF5101TCE" R0402 3353.67,6458.2 r180 top
R51 "0402WGF5101TCE" R0402 6847.16,6322.48 r0 top
R52 "0402WGF5101TCE" R0402 6848.9,3504.51 r0 top
R52 "0402WGF5101TCE" R0402 3354.6,3370.65 r180 top
R52 "0402WGF5101TCE" R0402 3353.94,4354.9 r180 top
R52 "0402WGF5101TCE" R0402 6848.23,4488.76 r0 top
R52 "0402WGF5101TCE" R0402 3353.94,5339.16 r180 top
R52 "0402WGF5101TCE" R0402 6848.23,5473.01 r0 top
R52 "0402WGF5101TCE" R0402 3353.27,6323.41 r180 top
R52 "0402WGF5101TCE" R0402 6847.56,6457.27 r0 top
R53 "0402WGF2002TCE" R0402 5718.05,3402.33 r0 top
R53 "0402WGF2002TCE" R0402 4485.45,3472.83 r180 top
R53 "0402WGF2002TCE" R0402 4484.78,4457.09 r180 top
R53 "0402WGF2002TCE" R0402 5717.38,4386.58 r0 top
R53 "0402WGF2002TCE" R0402 4484.78,5441.34 r180 top
R53 "0402WGF2002TCE" R0402 5717.38,5370.83 r0 top
R53 "0402WGF2002TCE" R0402 4484.11,6425.59 r180 top
R53 "0402WGF2002TCE" R0402 5716.72,6355.08 r0 top
R54 "0402WGF5101TCE" R0402 5843.05,3272.33 r0 top
R54 "0402WGF5101TCE" R0402 4360.45,3602.83 r180 top
R54 "0402WGF5101TCE" R0402 4359.78,4587.09 r180 top
R54 "0402WGF5101TCE" R0402 5842.38,4256.58 r0 top
R54 "0402WGF5101TCE" R0402 4359.78,5571.34 r180 top
R54 "0402WGF5101TCE" R0402 5842.38,5240.83 r0 top
R54 "0402WGF5101TCE" R0402 4359.11,6555.59 r180 top
R54 "0402WGF5101TCE" R0402 5841.72,6225.08 r0 top
R56 "0402WGF1000TCE" R0402 5478.05,3257.33 r0 top
R56 "0402WGF1000TCE" R0402 4725.45,3617.83 r180 top
R56 "0402WGF1000TCE" R0402 4724.78,4602.09 r180 top
R56 "0402WGF1000TCE" R0402 5477.38,4241.58 r0 top
R56 "0402WGF1000TCE" R0402 4724.78,5586.34 r180 top
R56 "0402WGF1000TCE" R0402 5477.38,5225.83 r0 top
R56 "0402WGF1000TCE" R0402 4724.11,6570.59 r180 top
R56 "0402WGF1000TCE" R0402 5476.72,6210.08 r0 top
R57 "FRC0603F1001TS" R0603 6108.05,3226.65 r270 bottom
R57 "FRC0603F1001TS" R0603 4095.45,3648.51 r90 bottom
R57 "FRC0603F1001TS" R0603 4094.78,4632.77 r90 bottom
R57 "FRC0603F1001TS" R0603 6107.38,4210.9 r270 bottom
R57 "FRC0603F1001TS" R0603 4094.78,5617.02 r90 bottom
R57 "FRC0603F1001TS" R0603 6107.38,5195.15 r270 bottom
R57 "FRC0603F1001TS" R0603 4094.11,6601.27 r90 bottom
R57 "FRC0603F1001TS" R0603 6106.72,6179.4 r270 bottom
U6 "ATMEGA328P-AU_C14877" TQFP-32_L7.0-W7.0-P0.80-LS9.0-BL 6208.05,3467.33 r180 top
U6 "ATMEGA328P-AU_C14877" TQFP-32_L7.0-W7.0-P0.80-LS9.0-BL 3995.45,3407.83 r0 top
U6 "ATMEGA328P-AU_C14877" TQFP-32_L7.0-W7.0-P0.80-LS9.0-BL 3994.78,4392.09 r0 top
U6 "ATMEGA328P-AU_C14877" TQFP-32_L7.0-W7.0-P0.80-LS9.0-BL 6207.38,4451.58 r180 top
U6 "ATMEGA328P-AU_C14877" TQFP-32_L7.0-W7.0-P0.80-LS9.0-BL 3994.78,5376.34 r0 top
U6 "ATMEGA328P-AU_C14877" TQFP-32_L7.0-W7.0-P0.80-LS9.0-BL 6207.38,5435.83 r180 top
U6 "ATMEGA328P-AU_C14877" TQFP-32_L7.0-W7.0-P0.80-LS9.0-BL 3994.11,6360.59 r0 top
U6 "ATMEGA328P-AU_C14877" TQFP-32_L7.0-W7.0-P0.80-LS9.0-BL 6206.72,6420.08 r180 top
U8 "TP4056_C42422118" ESOP-8_L4.9-W3.9-P1.27-LS6.0-BL-EP-1 5378.05,3452.33 r90 top
U8 "TP4056_C42422118" ESOP-8_L4.9-W3.9-P1.27-LS6.0-BL-EP-1 4825.45,3422.83 r270 top
U8 "TP4056_C42422118" ESOP-8_L4.9-W3.9-P1.27-LS6.0-BL-EP-1 4824.78,4407.09 r270 top
U8 "TP4056_C42422118" ESOP-8_L4.9-W3.9-P1.27-LS6.0-BL-EP-1 5377.38,4436.58 r90 top
U8 "TP4056_C42422118" ESOP-8_L4.9-W3.9-P1.27-LS6.0-BL-EP-1 4824.78,5391.34 r270 top
U8 "TP4056_C42422118" ESOP-8_L4.9-W3.9-P1.27-LS6.0-BL-EP-1 5377.38,5420.83 r90 top
U8 "TP4056_C42422118" ESOP-8_L4.9-W3.9-P1.27-LS6.0-BL-EP-1 4824.11,6375.59 r270 top
U8 "TP4056_C42422118" ESOP-8_L4.9-W3.9-P1.27-LS6.0-BL-EP-1 5376.72,6405.08 r90 top
U9 "CH340N" SOP-8_L4.9-W3.9-P1.27-LS6.0-BL 6655.89,3438.39 r90 top
U9 "CH340N" SOP-8_L4.9-W3.9-P1.27-LS6.0-BL 3547.61,3436.77 r270 top
U9 "CH340N" SOP-8_L4.9-W3.9-P1.27-LS6.0-BL 3546.94,4421.02 r270 top
U9 "CH340N" SOP-8_L4.9-W3.9-P1.27-LS6.0-BL 6655.22,4422.64 r90 top
U9 "CH340N" SOP-8_L4.9-W3.9-P1.27-LS6.0-BL 3546.94,5405.28 r270 top
U9 "CH340N" SOP-8_L4.9-W3.9-P1.27-LS6.0-BL 6655.22,5406.89 r90 top
U9 "CH340N" SOP-8_L4.9-W3.9-P1.27-LS6.0-BL 3546.28,6389.53 r270 top
U9 "CH340N" SOP-8_L4.9-W3.9-P1.27-LS6.0-BL 6654.55,6391.15 r90 top
U10 "MT3608L" SOT-23-6_L2.9-W1.6-P0.95-LS2.8-BL_3 5613.05,3272.33 r90 top
U10 "MT3608L" SOT-23-6_L2.9-W1.6-P0.95-LS2.8-BL_3 4590.45,3602.83 r270 top
U10 "MT3608L" SOT-23-6_L2.9-W1.6-P0.95-LS2.8-BL_3 4589.78,4587.09 r270 top
U10 "MT3608L" SOT-23-6_L2.9-W1.6-P0.95-LS2.8-BL_3 5612.38,4256.58 r90 top
U10 "MT3608L" SOT-23-6_L2.9-W1.6-P0.95-LS2.8-BL_3 4589.78,5571.34 r270 top
U10 "MT3608L" SOT-23-6_L2.9-W1.6-P0.95-LS2.8-BL_3 5612.38,5240.83 r90 top
U10 "MT3608L" SOT-23-6_L2.9-W1.6-P0.95-LS2.8-BL_3 4589.11,6555.59 r270 top
U10 "MT3608L" SOT-23-6_L2.9-W1.6-P0.95-LS2.8-BL_3 5611.72,6225.08 r90 top
U12 "BRCL3160MF" SOT-23-6_L2.9-W1.6-P0.95-LS2.8-BL 5333.05,3282.33 r180 top
U12 "BRCL3160MF" SOT-23-6_L2.9-W1.6-P0.95-LS2.8-BL 4870.45,3592.83 r0 top
U12 "BRCL3160MF" SOT-23-6_L2.9-W1.6-P0.95-LS2.8-BL 4869.78,4577.09 r0 top
U12 "BRCL3160MF" SOT-23-6_L2.9-W1.6-P0.95-LS2.8-BL 5332.38,4266.58 r180 top
U12 "BRCL3160MF" SOT-23-6_L2.9-W1.6-P0.95-LS2.8-BL 4869.78,5561.34 r0 top
U12 "BRCL3160MF" SOT-23-6_L2.9-W1.6-P0.95-LS2.8-BL 5332.38,5250.83 r180 top
U12 "BRCL3160MF" SOT-23-6_L2.9-W1.6-P0.95-LS2.8-BL 4869.11,6545.59 r0 top
U12 "BRCL3160MF" SOT-23-6_L2.9-W1.6-P0.95-LS2.8-BL 5331.72,6235.08 r180 top
U13 "WS-003DB" SW-SMD_WS-003DB 5678.05,3657.33 r0 top
U13 "WS-003DB" SW-SMD_WS-003DB 4525.45,3217.83 r180 top
U13 "WS-003DB" SW-SMD_WS-003DB 4524.78,4202.09 r180 top
U13 "WS-003DB" SW-SMD_WS-003DB 5677.38,4641.58 r0 top
U13 "WS-003DB" SW-SMD_WS-003DB 4524.78,5186.34 r180 top
U13 "WS-003DB" SW-SMD_WS-003DB 5677.38,5625.83 r0 top
U13 "WS-003DB" SW-SMD_WS-003DB 4524.11,6170.59 r180 top
U15 "SLRR0564FR1C4BD-3.5A" LED-SEG-TH_14P-L50.2-W19.0-P2.54-S15.24-BL 6207.36,5406.08 r0 top
U15 "SLRR0564FR1C4BD-3.5A" LED-SEG-TH_14P-L50.2-W19.0-P2.54-S15.24-BL 3992.4,6390.34 r0 top
USB1 "GT-USB-7014D" USB-C-SMD_GT-USB-7014D 7007.36,3437.58 r90 top
USB1 "GT-USB-7014D" USB-C-SMD_GT-USB-7014D 3196.14,3437.58 r270 top
USB1 "GT-USB-7014D" USB-C-SMD_GT-USB-7014D 3195.47,4421.83 r270 top
USB1 "GT-USB-7014D" USB-C-SMD_GT-USB-7014D 7006.69,4421.83 r90 top
USB1 "GT-USB-7014D" USB-C-SMD_GT-USB-7014D 3195.47,5406.08 r270 top
USB1 "GT-USB-7014D" USB-C-SMD_GT-USB-7014D 7006.69,5406.08 r90 top
USB1 "GT-USB-7014D" USB-C-SMD_GT-USB-7014D 3194.8,6390.34 r270 top
USB1 "GT-USB-7014D" USB-C-SMD_GT-USB-7014D 7006.02,6390.34 r90 top
X1 "TAXM16M4RLBCCT2T" CRYSTAL-SMD_4P-L3.2-W2.5-BL 6638.05,3702.33 r270 top
X1 "TAXM16M4RLBCCT2T" CRYSTAL-SMD_4P-L3.2-W2.5-BL 3565.45,3172.83 r90 top
X1 "TAXM16M4RLBCCT2T" CRYSTAL-SMD_4P-L3.2-W2.5-BL 3564.78,4157.09 r90 top
X1 "TAXM16M4RLBCCT2T" CRYSTAL-SMD_4P-L3.2-W2.5-BL 6637.38,4686.58 r270 top
X1 "TAXM16M4RLBCCT2T" CRYSTAL-SMD_4P-L3.2-W2.5-BL 3564.78,5141.34 r90 top
X1 "TAXM16M4RLBCCT2T" CRYSTAL-SMD_4P-L3.2-W2.5-BL 6637.38,5670.83 r270 top
X1 "TAXM16M4RLBCCT2T" CRYSTAL-SMD_4P-L3.2-W2.5-BL 3564.11,6125.59 r90 top
X1 "TAXM16M4RLBCCT2T" CRYSTAL-SMD_4P-L3.2-W2.5-BL 6636.72,6655.08 r270 top

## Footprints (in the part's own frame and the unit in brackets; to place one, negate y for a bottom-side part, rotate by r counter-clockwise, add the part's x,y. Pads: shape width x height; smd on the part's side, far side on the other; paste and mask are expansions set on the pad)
C0402 [mm]
  rect 0.79x0.54 smd: 1(-0.545,0) 2(0.545,0)
  silkscreen extent -1.17,-0.5 1.17,0.5
CRYSTAL-SMD_4P-L3.2-W2.5-BL [mm]
  rect 1.4x1.2 smd: 1(-1.1,-0.85) 2(1.1,-0.85) 3(1.1,0.85) 4(-1.1,0.85)
  silkscreen extent -2.26,-1.91 2.03,1.68
ESOP-8_L4.9-W3.9-P1.27-LS6.0-BL-EP-1 [mm]
  oval 0.63x1.865 smd: 1(-1.905,-2.682) 2(-0.635,-2.682) 3(0.635,-2.682) 4(1.905,-2.682) 5(1.905,2.682) 6(0.635,2.682) 7(-0.635,2.682) 8(-1.905,2.682)
  rect 3.3x2.4 smd: 9(0,0)
  silkscreen extent -2.82,-2.83 2.58,1.52
L1206 [mm]
  rect 1.485x1.728 smd: 1(-1.593,0) 2(1.593,0)
  silkscreen extent -2.56,-1.09 2.56,1.09
LED-SEG-TH_14P-L50.2-W19.0-P2.54-S15.24-BL [mm]
  round 1.8 hole 0.9: 1(-7.62,-7.62) 2(-5.08,-7.62) 3(-2.54,-7.62) 4(0,-7.62) 5(2.54,-7.62) 6(5.08,-7.62) 7(7.62,-7.62) 8(7.62,7.62) 9(5.08,7.62) 10(2.54,7.62) 11(0,7.62) 12(-2.54,7.62) 13(-5.008,7.62) 14(-7.62,7.62)
  silkscreen extent -25.1,-9.53 25.15,9.53
LED-SEG-TH_SLR0564DBA4BD [mil]
  round 60 hole 36: 1(-300,-300) 2(-200,-300) 3(-100,-300) 4(0,-300) 5(100,-300) 6(200,-300) 7(300,-300) 8(300,300) 9(200,300) 10(100,300) 11(0,300) 12(-100,300) 13(-200,300) 14(-300,300)
  silkscreen extent -988,-374 988,374
LED-SEG-TH_SLRR0564DY2C4BD-6.3 [mil]
  round 60 hole 36: 1(-300,-300) 2(-200,-300) 3(-100,-300) 4(0,-300) 5(100,-300) 6(200,-300) 7(300,-300) 8(300,300) 9(200,300) 10(100,300) 11(0,300) 12(-100,300) 13(-200,300) 14(-300,300)
  silkscreen extent -988,-374 988,374
R0201 [mil]
  rect 11.93x12.76 smd: 1(-9.51,0) 2(9.51,0)
  silkscreen extent -24,-15 24,15
R0402 [mm]
  rect 0.566x0.54 smd: 1(-0.433,0) 2(0.433,0)
  silkscreen extent -0.94,-0.5 0.94,0.5
R0603 [mil]
  rect 31.75x34.02 smd: 1(-29.66,0) 2(29.66,0)
  silkscreen extent -55,-26 55,26
SOD-123_L2.8-W1.8-LS3.7-RD [mm]
  rect 0.95x1.15 smd: 1(-1.692,0) 2(1.692,0)
  silkscreen extent -1.58,-0.87 1.41,0.87
SOP-8_L4.9-W3.9-P1.27-LS6.0-BL [mm]
  oval 0.63x1.865 smd: 1(-1.905,-2.682) 2(-0.635,-2.682) 3(0.635,-2.682) 4(1.905,-2.682) 5(1.905,2.682) 6(0.635,2.682) 7(-0.635,2.682) 8(-1.905,2.682)
  silkscreen extent -2.5,-1.5 2.5,1.48
SOT-23-3_L2.9-W1.3-P1.90-LS2.4-BR [mm]
  rect 1.25x0.7 smd: 1(1,-0.95) 2(1,0.95) 3(-1,0)
  silkscreen extent -0.73,-1.53 0.73,1.53
SOT-23-6_L2.9-W1.6-P0.95-LS2.8-BL [mil]
  rect 20.95x42.2 smd: 1(-37.4,-45.24) 2(0,-45.24) 3(37.4,-45.24) 4(37.4,45.24) 5(0,45.24) 6(-37.4,45.24)
  silkscreen extent -72,-57 61,35
SOT-23-6_L2.9-W1.6-P0.95-LS2.8-BL_3 [mil]
  rect 20.95x42.2 smd: 1(-37.4,-45.24) 2(0,-45.24) 3(37.4,-45.24) 4(37.4,45.24) 5(0,45.24) 6(-37.4,45.24)
  silkscreen extent -72,-57 61,35
SW-SMD_WS-003DB [mm]
  rect 1x1.524 smd: 1(-3,-2.057) 2(-1,-2.057) 3(1,-2.057) 4(3,-2.057)
  rect 1x3 smd: 5(-4.75,-0.707) 5(4.75,-0.707)
  rect 1.2x1.28 smd rot 135: 5(-3.81,2.057)
  rect 1.2x1.28 smd rot 45: 5(3.81,2.056)
  Board Outline Layer circle w0.005: c-1.9,-0.207 r0.55
  Board Outline Layer circle w0.005: c1.9,-0.207 r0.55
  Board Outline Layer region: -1.35,-0.207 -1.404,-0.445 -1.557,-0.637 -1.778,-0.743 -2.022,-0.743 -2.243,-0.637 -2.396,-0.445 -2.45,-0.207 -2.45,-0.207 -2.396,0.032 -2.243,0.223 -2.022,0.33 -1.778,0.33 -1.557,0.223 -1.404,0.032 -1.35,-0.207
  Board Outline Layer region: 2.45,-0.207 2.396,-0.445 2.243,-0.637 2.022,-0.743 1.778,-0.743 1.557,-0.637 1.404,-0.445 1.35,-0.207 1.35,-0.207 1.404,0.032 1.557,0.223 1.778,0.33 2.022,0.33 2.243,0.223 2.396,0.032 2.45,-0.207
  Multi-Layer board cut-out: -1.35,-0.207 -1.404,-0.445 -1.557,-0.637 -1.778,-0.743 -2.022,-0.743 -2.243,-0.637 -2.396,-0.445 -2.45,-0.207 -2.45,-0.207 -2.396,0.032 -2.243,0.223 -2.022,0.33 -1.778,0.33 -1.557,0.223 -1.404,0.032 -1.35,-0.207
  Multi-Layer board cut-out: 2.45,-0.207 2.396,-0.445 2.243,-0.637 2.022,-0.743 1.778,-0.743 1.557,-0.637 1.404,-0.445 1.35,-0.207 1.35,-0.207 1.404,0.032 1.557,0.223 1.778,0.33 2.022,0.33 2.243,0.223 2.396,0.032 2.45,-0.207
  silkscreen extent -4.83,-2.67 4.83,5.53
TQFP-32_L7.0-W7.0-P0.80-LS9.0-BL [mm]
  oval 0.45x1.65 smd: 1(-2.8,-4.369) 2(-2,-4.369) 3(-1.2,-4.369) 4(-0.4,-4.369) 5(0.4,-4.369) 6(1.2,-4.369) 7(2,-4.369) 8(2.8,-4.369) 17(2.8,4.369) 18(2,4.369) 19(1.2,4.369) 20(0.4,4.369) 21(-0.4,4.369) 22(-1.2,4.369) 23(-2,4.369) 24(-2.8,4.369)
  oval 1.65x0.45 smd: 9(4.381,-2.8) 10(4.381,-2) 11(4.381,-1.2) 12(4.381,-0.4) 13(4.381,0.4) 14(4.381,1.2) 15(4.381,2) 16(4.381,2.8) 25(-4.381,2.8) 26(-4.381,2) 27(-4.381,1.2) 28(-4.381,0.4) 29(-4.381,-0.4) 30(-4.381,-1.2) 31(-4.381,-2) 32(-4.381,-2.8)
  silkscreen extent -3.91,-4.36 2.94,2.95
USB-C-SMD_GT-USB-7014D [mm]
  oval 1x2.2 hole 0.6 slot 1.8 at 90 deg: 0(-5.575,-2.55) 0(5.575,-2.55)
  oval 1x1.8 hole 0.6 slot 1.4 at 90 deg: 0(-5.575,1.45) 0(5.575,1.45)
  rect 0.6x1.1 smd: A1B12(-3.2,2.65) A4B9(-2.4,2.65) B1A12(3.2,2.65) B4A9(2.4,2.65)
  rect 0.3x1 smd: A5(-1.249,2.65) A6(-0.249,2.65) A7(0.251,2.65) A8(1.251,2.65) B6(0.751,2.65) B7(-0.749,2.65) B8(-1.749,2.65)
  rect 0.3x0.9 smd: B5(1.751,2.55)
  Board Outline Layer lines w0.254: -4.715,1.794 -4.715,-4.81 ; -4.715,1.794 4.683,1.794 ; -4.715,1.794 -4.715,-4.81 ; -4.715,1.794 4.683,1.794 ; 4.683,1.794 4.683,-4.81 ; 4.683,1.794 4.683,-4.81 ; -4.715,-4.81 -5.604,-4.81 -4.715,-4.81 ; 4.683,-4.81 5.572,-4.81 4.683,-4.81
  silkscreen extent -5.59,-4.83 5.59,2.54

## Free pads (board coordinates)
  round 36 hole 36: 73(3694.78,5706.34) 74(3794.68,5706.08) 75(3894.68,5706.08) 76(3994.68,5706.08) 77(4094.68,5706.08) 78(3694.68,5106.08) 79(3794.68,5106.08) 80(3894.68,5106.08) 81(3994.68,5106.08) 82(4094.68,5106.08) 83(4194.78,5106.34) 84(4294.78,5106.34) 85(4194.68,5706.08) 86(4294.68,5706.08) 91(3694.78,4722.09) 92(3794.68,4721.83) 93(3894.68,4721.83) 94(3994.68,4721.83) 95(4094.68,4721.83) 96(4194.68,4721.83) 97(4294.68,4721.83) 100(3694.68,4121.83) 101(3794.68,4121.83) 102(3894.68,4121.83) 103(3994.68,4121.83) 104(4094.68,4121.83) 105(4194.78,4122.09) 106(4294.78,4122.09)
  rect 196.85x196.85 smd far side: 87(4731,5156.34) 88(4731,5656.34) 89(5471.16,5155.83) 90(5471.16,5655.83) 98(4730.33,6640.59) 98(4731,4672.09) 99(5470.49,6640.08) 99(5471.16,4671.58) 107(4730.33,6140.59) 107(4731,4172.09) 108(5470.49,6140.08) 108(5471.16,4171.58) 123(4731.67,3187.83) 124(4731.67,3687.83) 125(5471.83,3687.33) 126(5471.83,3187.33)

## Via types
v1: diameter 24.02, hole 12.01, Top Layer to Bottom Layer, 312 vias

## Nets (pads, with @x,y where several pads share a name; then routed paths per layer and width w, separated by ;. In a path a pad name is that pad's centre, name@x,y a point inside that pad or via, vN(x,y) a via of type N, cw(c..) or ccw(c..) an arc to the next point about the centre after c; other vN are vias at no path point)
$1N3744: R51.2 USB1.A5 | length 443.7
  Top Layer w10: USB1.A5@3295.2,6439.5 3328.66,6439.5 3328.66,6447.59 3336.63,6455.56 R51.2@3336.63,6458.2 ; USB1.A5@3295.87,4470.99 3329.33,4470.99 3329.33,4479.08 3337.3,4487.05 R51.2@3337.3,4489.69 ; USB1.A5@3295.87,5455.24 3329.33,5455.24 3329.33,5463.34 3337.3,5471.3 R51.2@3337.3,5473.94 ; USB1.A5@3296.53,3486.74 3330,3486.74 3330,3494.83 3337.97,3502.8 R51.2@3337.97,3505.44 ; R51.2@6864.2,6322.48 6864.2,6325.12 6872.16,6333.09 6872.16,6341.18 USB1.A5@6905.63,6341.18 ; R51.2@6864.86,4353.97 6864.86,4356.61 6872.83,4364.58 6872.83,4372.67 USB1.A5@6906.3,4372.67 ; R51.2@6864.86,5338.22 6864.86,5340.86 6872.83,5348.83 6872.83,5356.92 USB1.A5@6906.3,5356.92 ; R51.2@6865.53,3369.72 6865.53,3372.36 6873.5,3380.33 6873.5,3388.42 USB1.A5@6906.96,3388.42
$1N7885: R50.1 U10.6 | length 577.7
  Top Layer w10: R50.1@4611.15,6655.59 4611.15,6616.19 U10.6@4634.35,6592.99 ; R50.1@4611.82,4687.09 4611.82,4647.68 U10.6@4635.02,4624.48 ; R50.1@4611.82,5671.34 4611.82,5631.94 U10.6@4635.02,5608.73 ; R50.1@4612.49,3702.83 4612.49,3663.43 U10.6@4635.69,3640.23 ; U10.6@5566.47,6187.69 5589.68,6164.48 R50.1@5589.68,6125.08 ; U10.6@5567.14,4219.18 5590.34,4195.98 R50.1@5590.34,4156.58 ; U10.6@5567.14,5203.43 5590.34,5180.23 R50.1@5590.34,5140.83 ; U10.6@5567.81,3234.93 5591.01,3211.73 R50.1@5591.01,3172.33
$1N10863: R48.1 U8.2 | length 714.5
  Top Layer w10: R48.1@4653.19,6342.63 4711.15,6400.59 U8.2@4718.5,6400.59 ; R48.1@4653.86,4374.13 4711.82,4432.09 U8.2@4719.17,4432.09 ; R48.1@4653.86,5358.38 4711.82,5416.34 U8.2@4719.17,5416.34 ; R48.1@4654.53,3389.87 4712.49,3447.83 U8.2@4719.84,3447.83 ; U8.2@5482.33,6380.08 5489.68,6380.08 R48.1@5547.64,6438.04 ; U8.2@5482.99,4411.58 5490.34,4411.58 R48.1@5548.3,4469.54 ; U8.2@5482.99,5395.83 5490.34,5395.83 R48.1@5548.3,5453.79 ; U8.2@5483.66,3427.33 5491.01,3427.33 R48.1@5548.97,3485.29
$1N11526: R49.1 R53.1 U10.3 | length 1020.1
  Top Layer w10: R53.1@4498.19,6427.63 4498.19,6451.51 4494.14,6455.56 4494.14,6493.52 4519.2,6493.52 U10.3@4543.87,6518.19 ; R53.1@4498.86,4459.13 4498.86,4483.01 4494.81,4487.05 R49.1@4494.78,4525.05 4519.87,4525.01 U10.3@4544.54,4549.68 ; R53.1@4498.86,5443.38 4498.86,5467.26 4494.81,5471.31 R49.1@4494.78,5509.3 4519.87,5509.27 U10.3@4544.54,5533.93 ; R53.1@4499.53,3474.87 4499.53,3498.75 4495.48,3502.8 4495.48,3540.76 4520.54,3540.76 U10.3@4545.21,3565.43 ; U10.3@5656.95,6262.49 5681.62,6287.15 5706.68,6287.15 5706.68,6325.11 5702.64,6329.16 R53.1@5702.64,6353.04 ; U10.3@5657.62,4293.98 5682.29,4318.65 R49.1@5707.38,4318.62 5707.35,4356.61 5703.3,4360.66 R53.1@5703.3,4384.54 ; U10.3@5657.62,5278.23 5682.29,5302.9 R49.1@5707.38,5302.87 5707.35,5340.86 5703.3,5344.91 R53.1@5703.3,5368.79 ; U10.3@5658.29,3309.73 5682.96,3334.4 5708.02,3334.4 5708.02,3372.36 5703.97,3376.41 R53.1@5703.97,3400.29
$1N11705: L5.2 U6.18 | length 2896
  Top Layer w10: L5.2@3761.81,6545.59 3794.11,6545.59 3824.57,6576.06 4064.11,6576.06 4072.85,6567.32 U6.18@4072.85,6532.59 ; L5.2@3762.48,4577.09 3794.78,4577.09 3825.24,4607.55 4064.78,4607.55 4073.52,4598.81 U6.18@4073.52,4564.09 ; L5.2@3762.48,5561.34 3794.78,5561.34 3825.24,5591.8 4064.78,5591.8 4073.52,5583.06 U6.18@4073.52,5548.34 ; L5.2@3763.15,3592.83 3795.45,3592.83 3825.91,3623.3 4065.45,3623.3 4074.19,3614.56 U6.18@4074.19,3579.83 ; U6.18@6127.98,6248.08 6127.98,6213.36 6136.72,6204.62 6376.25,6204.62 6406.72,6235.08 L5.2@6439.02,6235.08 ; U6.18@6128.64,4279.58 6128.64,4244.85 6137.38,4236.11 6376.92,4236.11 6407.38,4266.58 L5.2@6439.68,4266.58 ; U6.18@6128.64,5263.83 6128.64,5229.11 6137.38,5220.37 6376.92,5220.37 6407.38,5250.83 L5.2@6439.68,5250.83 ; U6.18@6129.31,3295.33 6129.31,3260.6 6138.05,3251.86 6377.59,3251.86 6408.05,3282.33 L5.2@6440.35,3282.33
$1N13291: L5.1 L6.2 | length 676.8
  Top Layer w10: L6.2@3551.81,6545.59 L5.1@3636.41,6545.59 ; L6.2@3552.48,4577.09 L5.1@3637.08,4577.09 ; L6.2@3552.48,5561.34 L5.1@3637.08,5561.34 ; L6.2@3553.15,3592.83 L5.1@3637.75,3592.83 ; L5.1@6564.42,6235.08 L6.2@6649.02,6235.08 ; L5.1@6565.08,4266.58 L6.2@6649.68,4266.58 ; L5.1@6565.08,5250.83 L6.2@6649.68,5250.83 ; L5.1@6565.75,3282.33 L6.2@6650.35,3282.33
$1N13433: L3.2 Q1.2 | length 1939.4
  Top Layer w10: L3.2@4389.11,6473.29 4421.41,6505.59 4449.11,6505.59 4459.11,6515.59 4459.11,6550.59 4474.11,6565.59 4494.11,6565.59 4501.18,6572.66 4501.18,6640.89 Q1.2@4501.51,6641.22 ; L3.2@4389.78,4504.79 4422.08,4537.09 4449.78,4537.09 4459.78,4547.09 4459.78,4582.09 4474.78,4597.09 4494.78,4597.09 4501.85,4604.16 4501.85,4672.39 Q1.2@4502.18,4672.72 ; L3.2@4389.78,5489.04 4422.08,5521.34 4449.78,5521.34 4459.78,5531.34 4459.78,5566.34 4474.78,5581.34 4494.78,5581.34 4501.85,5588.41 4501.85,5656.64 Q1.2@4502.18,5656.97 ; L3.2@4390.45,3520.53 4422.75,3552.83 4450.45,3552.83 4460.45,3562.83 4460.45,3597.83 4475.45,3612.83 4495.45,3612.83 4502.52,3619.9 4502.52,3688.13 Q1.2@4502.85,3688.46 ; Q1.2@5699.32,6139.45 5699.64,6139.78 5699.64,6208.01 5706.72,6215.08 5726.72,6215.08 5741.72,6230.08 5741.72,6265.08 5751.72,6275.08 5779.42,6275.08 L3.2@5811.72,6307.38 ; Q1.2@5699.98,4170.95 5700.31,4171.28 5700.31,4239.51 5707.38,4246.58 5727.38,4246.58 5742.38,4261.58 5742.38,4296.58 5752.38,4306.58 5780.08,4306.58 L3.2@5812.38,4338.88 ; Q1.2@5699.98,5155.2 5700.31,5155.53 5700.31,5223.76 5707.38,5230.83 5727.38,5230.83 5742.38,5245.83 5742.38,5280.83 5752.38,5290.83 5780.08,5290.83 L3.2@5812.38,5323.13 ; Q1.2@5700.65,3186.7 5700.98,3187.02 5700.98,3255.25 5708.05,3262.33 5728.05,3262.33 5743.05,3277.33 5743.05,3312.33 5753.05,3322.33 5780.75,3322.33 L3.2@5813.05,3354.63
$1N13465: D5.2 Q1.3 U10.1 | length 3212.3
  Top Layer w10: D5.2@4275.74,6595.59 4400.11,6719.96 4462.14,6719.96 v1(4464.11,6721.93) ; D5.2@4276.41,4627.09 4400.78,4751.46 4462.81,4751.46 v1(4464.78,4753.42) ; D5.2@4276.41,5611.34 4400.78,5735.71 4462.81,5735.71 v1(4464.78,5737.68) ; D5.2@4277.08,3642.83 4401.45,3767.2 4463.48,3767.2 v1(4465.45,3769.17) ; v1(5736.72,6058.74) 5738.68,6060.71 5800.72,6060.71 D5.2@5925.09,6185.08 ; v1(5737.38,4090.24) 5739.35,4092.21 5801.38,4092.21 D5.2@5925.75,4216.58 ; v1(5737.38,5074.49) 5739.35,5076.46 5801.38,5076.46 D5.2@5925.75,5200.83 ; v1(5738.05,3105.99) 5740.02,3107.96 5802.05,3107.96 D5.2@5926.42,3232.33
  Bottom Layer w10: v1(4464.11,6721.93) 4464.11,6669.99 v1(4541.12,6592.99) ; v1(4464.78,4753.42) 4464.78,4701.49 v1(4541.79,4624.48) ; v1(4464.78,5737.68) 4464.78,5685.74 v1(4541.79,5608.73) ; v1(4465.45,3769.17) 4465.45,3717.24 v1(4542.45,3640.23) ; v1(5659.71,6187.69) 5736.72,6110.68 v1(5736.72,6058.74) ; v1(5660.38,4219.18) 5737.38,4142.17 v1(5737.38,4090.24) ; v1(5660.38,5203.43) 5737.38,5126.43 v1(5737.38,5074.49) ; v1(5661.04,3234.93) 5738.05,3157.92 v1(5738.05,3105.99)
$1N14246: C24.1 R56.1 U12.5 | length 1238.2
  Top Layer w10: R56.1@4741.15,6570.59 4744.69,6574.13 C24.1@4794.11,6574.13 4801.3,6574.13 4816.69,6558.74 4846.73,6558.74 4869.11,6581.12 U12.5@4869.11,6590.83 ; R56.1@4741.82,4602.09 4745.36,4605.63 C24.1@4794.78,4605.63 4801.97,4605.63 4817.36,4590.24 4847.4,4590.24 4869.78,4612.62 U12.5@4869.78,4622.33 ; R56.1@4741.82,5586.34 4745.36,5589.88 C24.1@4794.78,5589.88 4801.97,5589.88 4817.36,5574.49 4847.4,5574.49 4869.78,5596.87 U12.5@4869.78,5606.58 ; R56.1@4742.49,3617.83 4746.03,3621.37 C24.1@4795.45,3621.37 4802.64,3621.37 4818.02,3605.99 4848.07,3605.99 4870.45,3628.36 U12.5@4870.45,3638.07 ; U12.5@5331.72,6189.84 5331.72,6199.55 5354.09,6221.93 5384.14,6221.93 5399.52,6206.54 C24.1@5406.72,6206.54 5456.14,6206.54 R56.1@5459.68,6210.08 ; U12.5@5332.38,4221.34 5332.38,4231.05 5354.76,4253.42 5384.81,4253.42 5400.19,4238.04 C24.1@5407.38,4238.04 5456.8,4238.04 R56.1@5460.34,4241.58 ; U12.5@5332.38,5205.59 5332.38,5215.3 5354.76,5237.68 5384.81,5237.68 5400.19,5222.29 C24.1@5407.38,5222.29 5456.8,5222.29 R56.1@5460.34,5225.83 ; U12.5@5333.05,3237.09 5333.05,3246.79 5355.43,3269.17 5385.47,3269.17 5400.86,3253.79 C24.1@5408.05,3253.79 5457.47,3253.79 R56.1@5461.01,3257.33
